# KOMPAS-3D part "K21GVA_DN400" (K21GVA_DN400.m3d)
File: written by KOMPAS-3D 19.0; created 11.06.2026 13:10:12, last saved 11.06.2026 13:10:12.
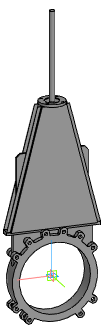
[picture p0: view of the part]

Document properties: Автор: Энергия; Полное имя файла: Z:\3.Личные\kachalov\001_3d для проектировщиков\2.5 Тип_K21GVA. Задвижка\_stp\_stp_K21GVA_DN50-DN1000_с фланцем\K21GVA_DN400.m3d

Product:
- Part/product: K21GVA_DN400

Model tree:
1. Операция без истории:1  (labels: K21GVA_DN400)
